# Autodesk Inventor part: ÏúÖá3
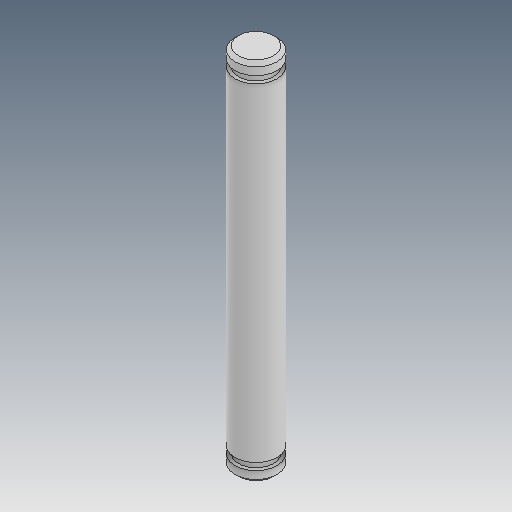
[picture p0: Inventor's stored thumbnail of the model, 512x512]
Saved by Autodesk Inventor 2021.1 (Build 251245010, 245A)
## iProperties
Created: 2013-04
Part Number: ÏúÖá3
Material: Ogólny
Document SubType Name: Modeling
Designer: user
Density: 1 g/cm^3
Appearance: Domyślna
Author: user
Revision Number: ÈÎºÎ
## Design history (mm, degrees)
feature "Ðý×ª1"
node "Bryła1"
